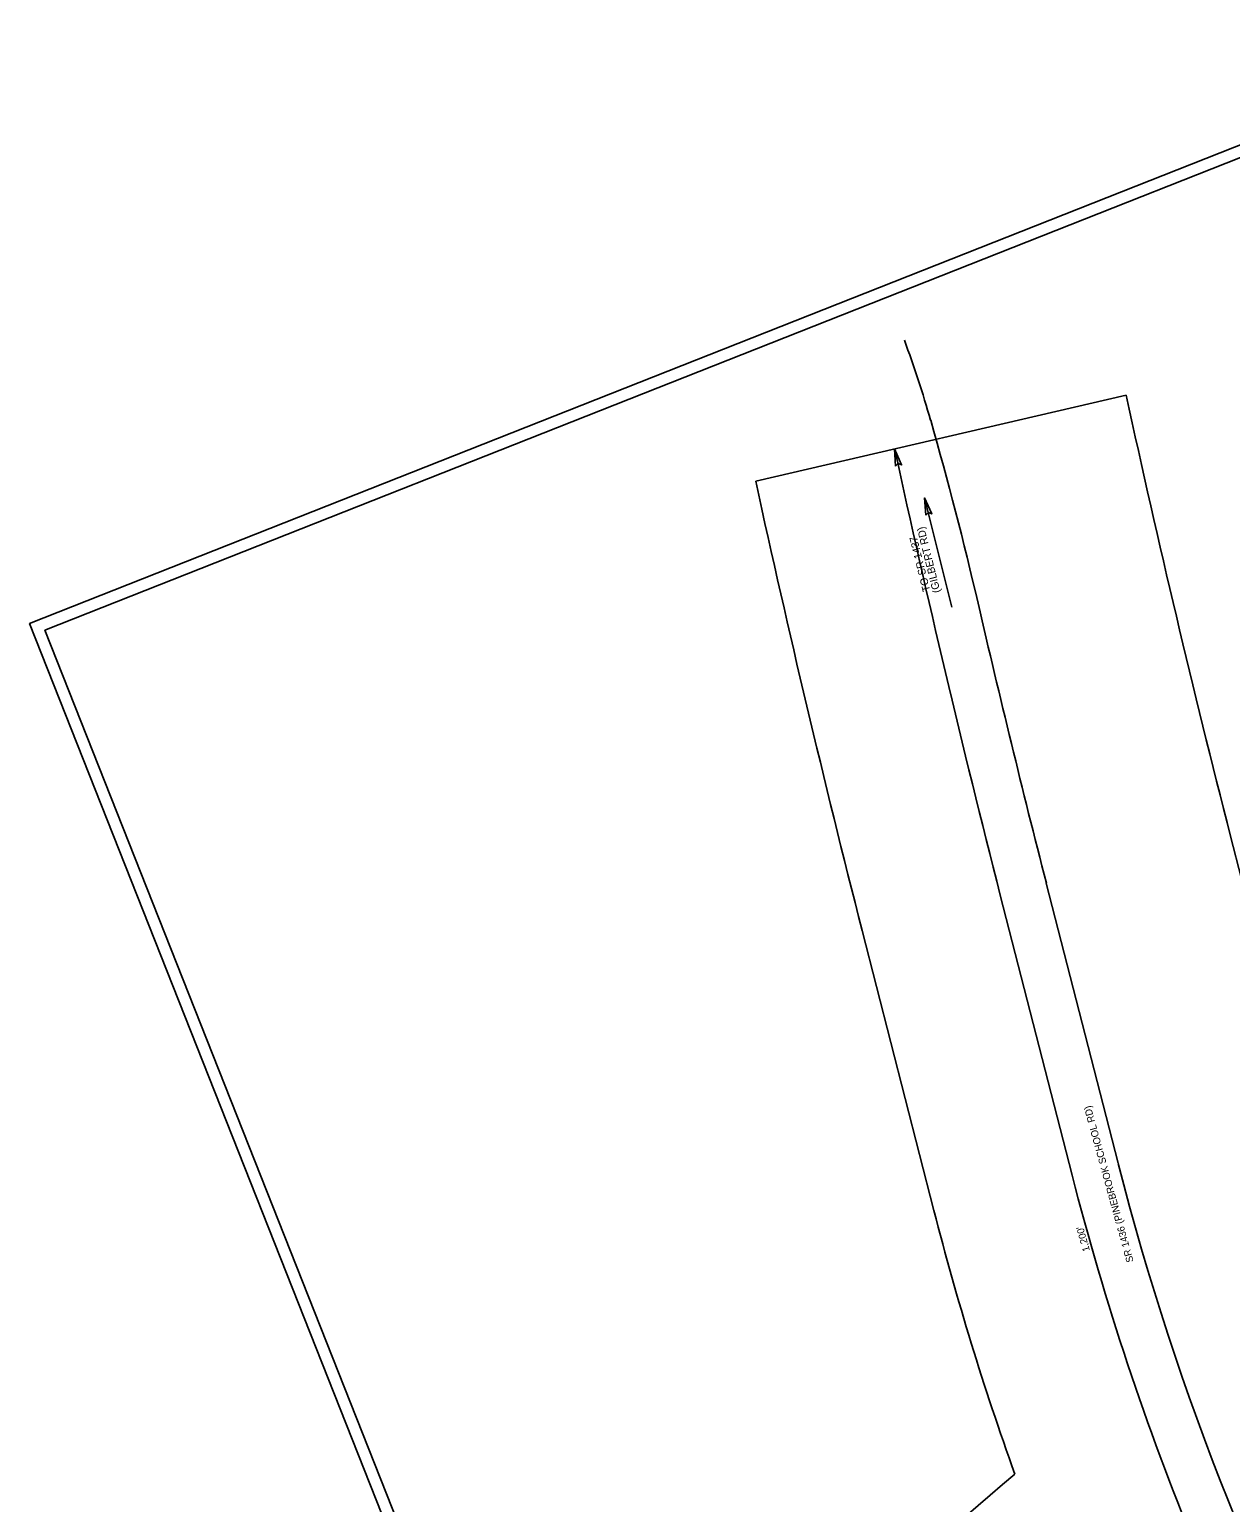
# Model space of a CAD drawing. Extents: x 1550555 to 1553129, y 809174 to 812311.
# Drawn here: x 1550555 to 1551819, y 810761 to 812311 of the extents above; entities that cross this region are included whole.
import ezdxf

# ---------------------------------------------------------------- set-up
doc = ezdxf.new("R2010")
doc.units = 0
for name, color, linetype in [('Old_Level_1', 7, 'Continuous'), ('P_RDY_Dimension', 7, 'Continuous'), ('P_RDY_Dimension_Text', 7, 'Continuous'), ('P_RDY_Terminator_Cell', 7, 'Continuous'), ('Pattern_4', 7, 'Continuous'), ('Site_Temp_Construction', 7, 'Continuous')]:
    doc.layers.add(name, color=color, linetype=linetype)

msp = doc.modelspace()

# ---------------------------------------------------------------- linework, layer by layer
at = {"layer": 'Old_Level_1'}
for points in [[(1552136.2, 812311.3), (1553129.1, 809800.4), (1551548.3, 809175.3), (1550555.4, 811686.1)], [(1552129.2, 812295), (1553112.9, 809807.5), (1551555.3, 809191.5), (1550571.6, 811679.1)]]:
    msp.add_lwpolyline(points, close=True, dxfattribs=at)
at = {"layer": 'P_RDY_Dimension'}
msp.add_line((1551576.6, 811400.5), (1551652.1, 811105.8), dxfattribs=at)
for centre, radius, start, end in [((1564422.1, 814690), 13260, 192.2791, 194.36371), ((1554498, 811834.5), 2937.7, 194.3637, 202.4345)]:
    msp.add_arc(centre, radius, start, end, dxfattribs=at)
at = {"layer": 'P_RDY_Terminator_Cell'}
for points in [[(1551466.5, 811851.7), (1551465.4, 811869.9), (1551472.7, 811853.1), (1551469, 811854.6)], [(1551498.4, 811800.1), (1551497, 811818.3), (1551504.5, 811801.5), (1551500.9, 811803)]]:
    msp.add_lwpolyline(points, close=True, dxfattribs=at)
at = {"layer": 'Pattern_4'}
msp.add_line((1551700.5, 811118.2), (1551625, 811412.9), dxfattribs=at)
for centre, radius, start, end in [((1550369.5, 811575.2), 1179.4, 15.9909, 20.2988), ((1547780.6, 810833.2), 3872.6, 13.0483, 15.9909), ((1564422.1, 814690), 13210, 193.04825, 194.36371), ((1554498, 811834.5), 2887.7, 194.3637, 209.2123), ((1543473.3, 820207.4), 12632.8, 308.90318, 313.63201)]:
    msp.add_arc(centre, radius, start, end, dxfattribs=at)
at = {"layer": 'Site_Temp_Construction'}
for p, q in [((1551319.3, 811836.1), (1551709, 811926.4)), ((1551525.6, 811703.3), (1551497, 811818.3)), ((1551894.3, 811167.8), (1551818.8, 811462.5)), ((1551506.8, 811068.6), (1551431.3, 811363.3))]:
    msp.add_line(p, q, dxfattribs=at)
for centre, radius, start, end in [((1564422.1, 814690), 13010, 192.26432, 194.36371), ((1564422.1, 814690), 13410, 192.2877, 194.36371), ((1554498, 811834.5), 3087.7, 194.3637, 199.7481), ((1543473.3, 820207.4), 12432.8, 308.26298, 310.76768)]:
    msp.add_arc(centre, radius, start, end, dxfattribs=at)

# ---------------------------------------------------------------- texts
at = {"layer": 'P_RDY_Dimension_Text'}
for s, height, rotation, p in [('(GILBERT RD)', 8, 103.9513, (1551513.7, 811719.4)), ('TO SR 1437', 8, 103.9513, (1551503, 811720.8)), ('SR 1436 (PINEBROOK SCHOOL RD)', 7.5, 105.4026, (1551716.9, 811015)), ("1,200'", 7.5, 105.6826, (1551670.9, 811026.5))]:
    msp.add_text(s, height=height, rotation=rotation, dxfattribs=at).set_placement(p)

doc.saveas('drawing.dxf')
